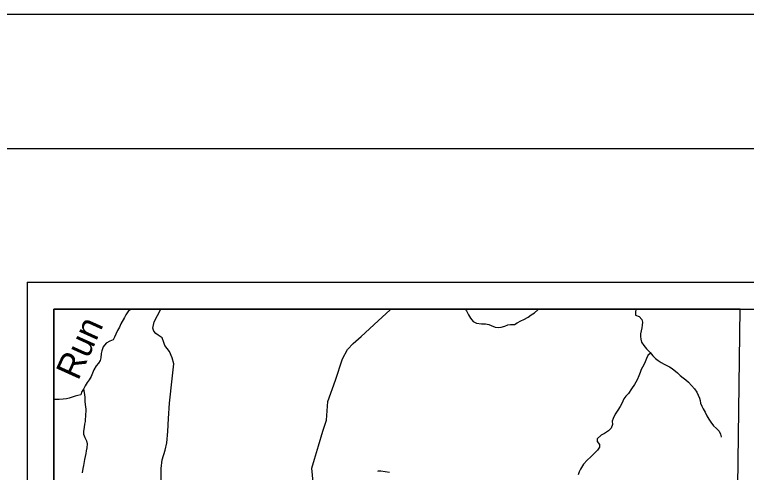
# Model space of a CAD drawing. Extents: x 0 to 34, y 0 to 22.
# Drawn here: x 1.953 to 4.685, y 20.29 to 22 of the extents above; entities that cross this region are included whole.
import ezdxf

# ---------------------------------------------------------------- set-up
doc = ezdxf.new("R2010")
doc.units = 0
for name, color, linetype in [('GM_X_Corporation', 7, 'Continuous'), ('GM_X_County_Road', 7, 'Continuous'), ('GM_X_Major_River', 7, 'Continuous'), ('GM_X_Minor_River', 7, 'Continuous'), ('GM_X_Minor_River_Text', 7, 'Continuous'), ('GM_X_Township_Road', 7, 'Continuous'), ('SH_Border', 7, 'Continuous'), ('SH_Cut_Line', 7, 'Continuous'), ('SH_Data', 7, 'Continuous')]:
    doc.layers.add(name, color=color, linetype=linetype)

msp = doc.modelspace()

# ---------------------------------------------------------------- linework, layer by layer
at = {"layer": 'GM_X_Corporation'}
msp.add_lwpolyline([(4.6083, 17.0396), (4.6111, 17.2406), (4.6176, 17.7005), (4.6283, 18.459), (4.6386, 19.1863), (4.6534, 20.2382), (4.6627, 20.9), (2.1, 20.9), (2.1, 17.0396)], dxfattribs=at)
at = {"layer": 'GM_X_County_Road'}
msp.add_lwpolyline([(2.4997, 20.2565), (2.4998, 20.3048), (2.5041, 20.3371), (2.5147, 20.3723), (2.521, 20.3998), (2.5246, 20.4424), (2.5278, 20.4911), (2.5315, 20.5485), (2.5414, 20.6394), (2.5474, 20.6953), (2.5409, 20.718), (2.5309, 20.7413), (2.5145, 20.7637), (2.5108, 20.7746), (2.5037, 20.7919), (2.4894, 20.8026), (2.4802, 20.8089), (2.4728, 20.8167), (2.4691, 20.8284), (2.4736, 20.8528), (2.4991, 20.9)], dxfattribs=at)
at = {"layer": 'GM_X_Major_River'}
msp.add_lwpolyline([(3.6372, 20.9), (3.6407, 20.8929), (3.6478, 20.8786), (3.6552, 20.8658), (3.6649, 20.8535), (3.6779, 20.8469), (3.6969, 20.845), (3.7117, 20.8445), (3.7235, 20.8425), (3.733, 20.8388), (3.7468, 20.8323), (3.7593, 20.831), (3.7692, 20.8319), (3.7839, 20.836), (3.7952, 20.8408), (3.805, 20.8425), (3.819, 20.842), (3.8295, 20.8486), (3.8438, 20.8553), (3.8547, 20.8609), (3.8701, 20.8695), (3.8817, 20.8788), (3.8937, 20.8862), (3.9068, 20.8964), (3.9093, 20.9)], dxfattribs=at)
at = {"layer": 'GM_X_Minor_River'}
for points in [[(2.3914, 20.9), (2.3889, 20.8993), (2.3779, 20.8927), (2.3682, 20.8789), (2.363, 20.8689), (2.3496, 20.8448), (2.3441, 20.8325), (2.3374, 20.8199), (2.3307, 20.8061), (2.3259, 20.7946), (2.3215, 20.785), (2.3086, 20.7803), (2.2946, 20.7725), (2.2838, 20.7587), (2.2786, 20.7434), (2.2765, 20.7338), (2.2744, 20.7178), (2.2719, 20.7079), (2.2667, 20.6979), (2.2573, 20.6875), (2.2491, 20.6726), (2.244, 20.6603), (2.2388, 20.6485), (2.2313, 20.6358), (2.2242, 20.6254), (2.2164, 20.6135), (2.2097, 20.6009), (2.2034, 20.5898), (2.2009, 20.5798), (2.1895, 20.577), (2.1789, 20.5742), (2.1675, 20.5702), (2.1569, 20.5671), (2.147, 20.565), (2.1345, 20.5629), (2.1189, 20.5623), (2.1037, 20.5621), (2.1, 20.562)], [(4.2722, 20.9), (4.2721, 20.8997), (4.2712, 20.8872), (4.2713, 20.8769), (4.2851, 20.8725), (4.2955, 20.8612), (4.2971, 20.851), (4.2965, 20.8392), (4.2948, 20.8293), (4.2922, 20.8182), (4.2897, 20.8068), (4.2895, 20.7973), (4.2907, 20.7878), (4.2943, 20.7768), (4.3021, 20.764), (4.3125, 20.7512), (4.326, 20.7373), (4.3365, 20.7256), (4.3457, 20.7155), (4.3557, 20.708), (4.3668, 20.7002), (4.3784, 20.6935), (4.3887, 20.6891), (4.3983, 20.6846), (4.4079, 20.6783), (4.4279, 20.6619), (4.4386, 20.6521), (4.4494, 20.6427), (4.4594, 20.6353), (4.4698, 20.6267), (4.4806, 20.6146), (4.4918, 20.6015), (4.5, 20.589), (4.5101, 20.5675), (4.5125, 20.558), (4.5146, 20.5478), (4.5185, 20.5372), (4.5236, 20.5274), (4.531, 20.5145), (4.538, 20.5013), (4.5454, 20.4888), (4.5524, 20.4768), (4.5625, 20.464), (4.5744, 20.4542), (4.5836, 20.4437), (4.5884, 20.4324), (4.5911, 20.4225), (4.5919, 20.421)], [(4.3277, 20.7354), (4.3174, 20.7261), (4.313, 20.715), (4.3049, 20.697), (4.2971, 20.6832), (4.2926, 20.6737), (4.2889, 20.6633), (4.2842, 20.6503), (4.2771, 20.635), (4.2678, 20.6182), (4.257, 20.6013), (4.2451, 20.5844), (4.2353, 20.5743), (4.2282, 20.564), (4.2201, 20.5475), (4.2145, 20.5364), (4.2059, 20.5222), (4.1958, 20.5068), (4.1877, 20.4907), (4.1844, 20.4808), (4.1853, 20.4682), (4.1805, 20.4552), (4.17, 20.4448), (4.1557, 20.4355), (4.1432, 20.4288), (4.1285, 20.4145), (4.1287, 20.405), (4.1364, 20.3941), (4.1369, 20.3842), (4.1291, 20.3723), (4.1156, 20.3588), (4.105, 20.348), (4.0908, 20.3349), (4.0769, 20.3198), (4.0664, 20.3022), (4.0616, 20.2918), (4.0572, 20.2807)], [(2.2101, 20.6017), (2.2133, 20.5884), (2.2147, 20.5701), (2.2157, 20.5534), (2.2178, 20.5352), (2.2187, 20.5257), (2.2183, 20.499), (2.2169, 20.4891), (2.2159, 20.4796), (2.2145, 20.4693), (2.2127, 20.4586), (2.2106, 20.4422), (2.2104, 20.432), (2.2155, 20.4202), (2.2214, 20.4078), (2.2238, 20.3964), (2.2225, 20.3808), (2.2207, 20.3708), (2.2185, 20.3602), (2.216, 20.3487), (2.2135, 20.3376), (2.21, 20.3155), (2.2078, 20.3048), (2.2058, 20.2877)], [(3.3108, 20.2939), (3.3082, 20.2931)], [(3.3531, 20.2888), (3.3367, 20.2912), (3.3207, 20.2937), (3.3108, 20.2939)]]:
    msp.add_lwpolyline(points, dxfattribs=at)
at = {"layer": 'GM_X_Township_Road'}
msp.add_lwpolyline([(3.0679, 20.2532), (3.0628, 20.3057), (3.0728, 20.3389), (3.0875, 20.3894), (3.1039, 20.4432), (3.1177, 20.4854), (3.1228, 20.5546), (3.1512, 20.6344), (3.177, 20.7139), (3.1964, 20.749), (3.2167, 20.7709), (3.2469, 20.7976), (3.3111, 20.8558), (3.355, 20.8966), (3.3582, 20.9)], dxfattribs=at)
at = {"layer": 'SH_Border'}
msp.add_lwpolyline([(1.5, 21.5), (33.5, 21.5), (33.5, 0.5), (1.5, 0.5)], close=True, dxfattribs=at)
at = {"layer": 'SH_Cut_Line'}
msp.add_lwpolyline([(0, 0), (34, 0), (34, 22), (0, 22)], close=True, dxfattribs=at)
at = {"layer": 'SH_Data'}
for q in [(9, 21), (2, 14)]:
    msp.add_line((2, 21), q, dxfattribs=at)
msp.add_lwpolyline([(2.1, 20.9), (8.9, 20.9), (8.9, 14.1), (2.1, 14.1)], close=True, dxfattribs=at)

# ---------------------------------------------------------------- texts
at = {"layer": 'GM_X_Minor_River_Text'}
msp.add_text('Run', height=0.09474, rotation=65.6387, dxfattribs=at).set_placement((2.1903, 20.6299))

doc.saveas('drawing.dxf')
